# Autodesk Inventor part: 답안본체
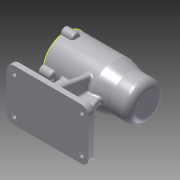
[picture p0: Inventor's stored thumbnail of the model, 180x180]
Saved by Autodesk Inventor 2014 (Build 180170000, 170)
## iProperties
Created: 2019-07
Part Number: 답안본체
Material: 알루미늄 6061
Document SubType Name: Modeling
Designer: net
Density: 2.71 g/cm^3
Appearance: 알루미늄 - 평지
Mass: 645.24 g
Surface Area: 658.047 cm^2
Volume: 238.096 cm^3
Author: net
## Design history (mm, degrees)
sketch "스케치1"
  geometry: L1 (-56, 0)-(56, 0); L2 (56, 0)-(56, 30); L3 (56, 30)-(-11, 30); L4 (-56, 0)-(-56, 25); L5 (-56, 25)-(-31, 25); L6 (-31, 25)-(-11, 30); L7 (56, 21)-(41, 21); L8 (41, 21)-(41, 21); L9 (38, 24)-(-10, 24); L10 (-13, 21)-(-13, 21); L11 (-13, 21)-(-24.7, 21); L12 (-25, 20.7)-(-25, 17.5); L13 (-25, 17.5)-(-42.7, 17.5); L14 (-43, 17.2)-(-43, 16); L15 (-43, 16)-(-46.7, 16); L16 (-47, 15.7)-(-47, 10.5); L17 (-47, 10.5)-(-47, 10.5); L18 (-50, 7.5)-(-50, 0); A1 r 3 centre (-47, 7.5) between (-47, 10.5) and (-50, 7.5); A2 r 0.3 centre (-46.7, 15.7) between (-46.7, 16) and (-47, 15.7); A3 r 0.3 centre (-42.7, 17.2) between (-42.7, 17.5) and (-43, 17.2); A4 r 0.3 centre (-24.7, 20.7) between (-24.7, 21) and (-25, 20.7); A5 r 3 centre (-10, 21) between (-10, 24) and (-13, 21); A6 r 3 centre (38, 21) between (41, 21) and (38, 24); 8 further points
  constraints: 36 end point, 14 point on line, 12 point on circle, 12 tangent, 9 perpendicular, 6 centre point, 6 parallel, 3 equal radius, 1 coincident, 1 collinear, 1 horizontal, 1 midpoint
  dimensions: "d0" = 112 distance of L1.start L1.end; "d1" = 67 distance of L2.end L3.end; "d2" = 60 diameter of L3 L1; "d3" = 50 diameter of L5 L1; "d4" = 25 distance of L4.end L5.end; "d5" = 15 distance of L7.start L7.end; "d6" = 3 distance of L16.end point (-50, 10.5); "d7" = 4 distance of L14.end point (-47, 16); "d8" = 18 distance of L12.end point (-43, 17.5); "d9" = 12 distance of L10.end point (-25, 21); "d10" = 54 distance of point (41, 24) point (-13, 24); "d11" = 21 diameter of L17 L1; "d12" = 32 diameter of L15 L1; "d13" = 35 diameter of L13 L1; "d14" = 42 diameter of L11 L1; "d15" = 48 diameter of L9 L1; "d16" = 42 diameter of L7 L1; "d17" = 3 radius of A1; "d18" = 0.3 radius of A2; "d77" = 3 radius of A5
revolve "회전1" sketch "스케치1" stored, may be unused: angle "d19" = 90 deg
fillet "모깎기1" dims "d20" = 10
fillet "모깎기2" dims "d21" = 3
sketch "스케치2"
  geometry: C1 r 30 at (0, 0) reference; C2 r 21 at (0, 0) reference
sketch "스케치3"
  geometry: C1 r 6 at (0, 30); 1 further point
  constraints: 1 centre point, 1 vertical alignment, 1 other
  dimensions: "d22" = 12 diameter of C1
extrude "돌출1" join sketch "스케치3" distance "d23" = 16; taper "d24" = 0 deg
fillet "모깎기3" dims "d25" = 3
fillet "모깎기4" dims "d26" = 1
fillet "모깎기5" dims "d30" = 3
fillet "모깎기6" dims "d31" = 1
sketch "스케치4"
  geometry: A1 r 6 centre (0, 0) between (5.998, 0.171) and (-5.998, 0.171) reference; A2 r 6 centre (-30, -30) between (-30.171, -24.002) and (-30.171, -35.998) reference; A3 r 6 centre (0, -60) between (-5.998, -60.171) and (5.998, -60.171) reference; A4 r 6 centre (30, -30) between (30.171, -35.998) and (30.171, -24.002) reference
hole "구멍1" sketch "스케치4" at (-30, -30), (0, -60), (30, -30), (0, 0) diameter "d32" = 3.242; stored, may be unused: countersink angle "d36" = 90 deg, drill point angle "d38" = 118 deg; dims "d33" = 8, "d34" = 4, "d35" = 2, "d37" = 11
node "작업 평면1"
sketch "스케치6"
  geometry: L1 (-56, -35)-(56, -35); L2 (56, -35)-(56, 35); L3 (56, 35)-(-56, 35); L4 (-56, 35)-(-56, -35); L5 (-56, -35)-(56, 35); L6 (56, -35)-(-56, 35); 1 further point
  constraints: 12 end point, 2 midpoint, 2 parallel, 1 horizontal, 1 perpendicular
  dimensions: "d40" = 112 distance of L2.end L3.end; "d41" = 70 distance of L3.end L1.start
extrude "돌출2" join sketch "스케치6" distance "d42" = 10; taper "d43" = 0 deg
chamfer "모따기1" distance "d44" = 1; stored, may be unused: second distance "d45" = 2, angle "d46" = 45 deg
fillet "모깎기7" dims "d47" = 10
sketch "스케치7"
  geometry: L1 (56, -25)-(56, 25) reference; L2 (46, 35)-(-46, 35) reference; L3 (-56, 25)-(-56, -25) reference; L4 (-4, -28)-(4, -28); L5 (4, -28)-(4, 28); L6 (4, 28)-(-4, 28); L7 (-4, 28)-(-4, -28); L8 (-4, -28)-(4, 28); L9 (4, -28)-(-4, 28); L10 (-31, -4)-(36, -4); L11 (36, -4)-(36, 4); L12 (36, 4)-(-31, 4); L13 (-31, 4)-(-31, -4); 3 further points
  constraints: 20 end point, 4 midpoint, 4 parallel, 2 horizontal, 2 perpendicular, 1 horizontal alignment
  dimensions: "d49" = 8 distance of L5.end L6.end; "d50" = 7 distance between parallel lines of L2 L6; "d54" = 8 distance of L12.end L10.start; "d55" = 25 distance between parallel lines of L13 L3; "d56" = 20 distance between parallel lines of L1 L11
extrude "돌출3" join sketch "스케치7" stored distance "d57" = 10; taper "d58" = 0 deg
feature "면 기울기1" dims angle "d60" = 20 deg
feature "면 기울기2" dims angle "d61" = 10 deg
chamfer "모따기2" distance "d62" = 3; stored, may be unused: second distance "d63" = 2, angle "d64" = 45 deg
fillet "모깎기9" dims "d65" = 3
fillet "모깎기10" dims "d66" = 3
sketch "스케치8"
  geometry: A1 r 7 centre (46, -25) between (46, -32) and (53, -25) reference; A2 r 7 centre (46, 25) between (53, 25) and (46, 32) reference; A3 r 7 centre (-46, 25) between (-46, 32) and (-53, 25) reference; A4 r 7 centre (-46, -25) between (-53, -25) and (-46, -32) reference; 1 further point
hole "구멍2" sketch "스케치8" at (-46, 25), (-46, -25), (46, -25), (46, 25) diameter "d67" = 6; stored, may be unused: countersink angle "d71" = 90 deg, drill point angle "d73" = 118 deg; dims "d68" = 8, "d69" = 4, "d70" = 2, "d72" = 11
node "작업 평면2"
sketch "스케치9"
  geometry: L1 (33.5, -29.226)-(33.5, -6.771) reference; 2 further points
  constraints: 1 horizontal alignment, 1 other
  dimensions: "d74" = 42 distance from line of L1 point (-8.5, 0)
feature "엠보싱1" sketch "스케치9" dims "d0" = 112, "d1" = 67, "d2" = 60, "d3" = 50, "d4" = 25, "d5" = 15, "d6" = 3, "d7" = 4, "d8" = 18, "d9" = 12, "d10" = 54, "d11" = 21, "d12" = 32, "d13" = 35, "d14" = 42, "d15" = 48, "d16" = 42, "d17" = 3, "d18" = 0.3, "d75" = 0.5, "d76" = 0, "d77" = 3
node "솔리드1"
pattern_circular "원형 패턴1" dims angle "d28" = 360 deg
